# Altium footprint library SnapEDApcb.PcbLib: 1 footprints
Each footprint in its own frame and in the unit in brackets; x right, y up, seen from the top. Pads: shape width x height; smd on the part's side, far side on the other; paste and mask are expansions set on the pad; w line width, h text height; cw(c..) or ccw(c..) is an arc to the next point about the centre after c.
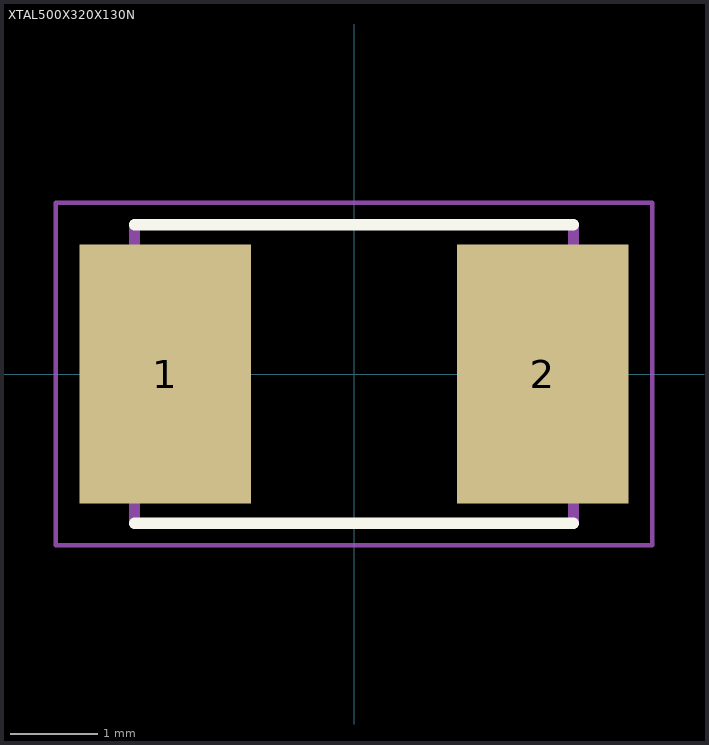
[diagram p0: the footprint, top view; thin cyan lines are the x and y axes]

## XTAL500X320X130N [mm]
pads (2):
  rect 1.95x2.95 smd: 1(-2.15,0) 2(2.15,0)
Top Overlay:
  lines w0.127: -2.5,-1.7 2.5,-1.7 ; -2.5,1.7 2.5,1.7
Mechanical 13:
  lines w0.127: -2.5,-1.7 -2.5,1.7 ; 2.5,-1.7 2.5,1.7
Mechanical 15:
  lines w0.05: -3.4,-1.95 3.4,-1.95 3.4,1.95 -3.4,1.95 -3.4,-1.95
